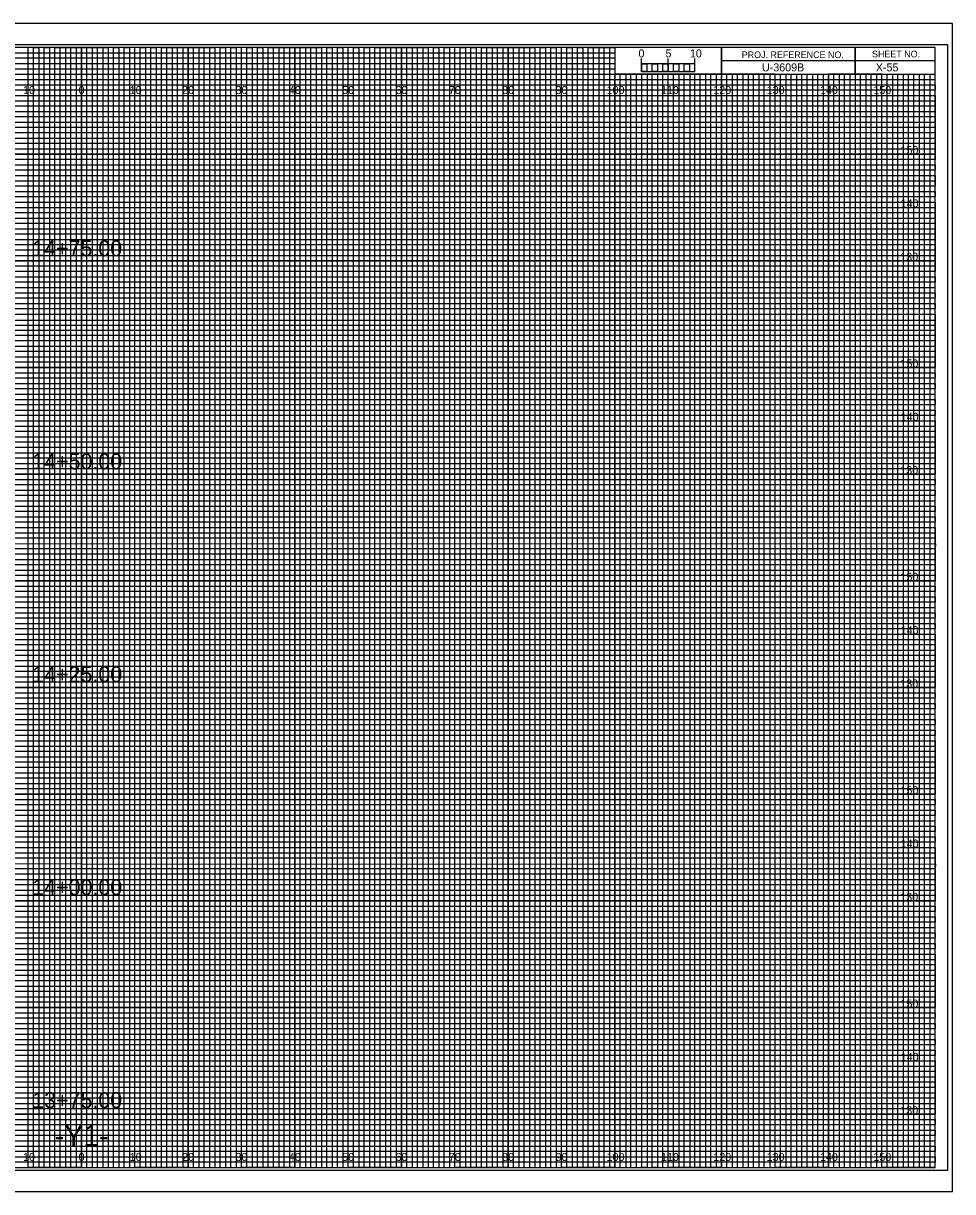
# Model space of a CAD drawing. Extents: x -13 to 323, y -5 to 2634.
# Drawn here: x 149.1 to 323.3, y 655.5 to 874.5 of the extents above; entities that cross this region are included whole.
import ezdxf

# ---------------------------------------------------------------- set-up
doc = ezdxf.new("R2010")
doc.units = 0
for name, color, linetype in [('Exist Cross Section Cell', 7, 'Continuous'), ('Exist XS Center Line Elevation Label', 7, 'Continuous'), ('Exist XS Ground Line', 7, 'Continuous'), ('Prop CMT Pvmt Course 1', 7, 'Continuous'), ('Prop CMT Pvmt Course 1 Wedge', 7, 'Continuous'), ('Prop CMT Pvmt Course 2', 7, 'Continuous'), ('Prop CMT Pvmt Course 2 Wedge', 7, 'Continuous'), ('Prop CMT Pvmt Course 3', 7, 'Continuous'), ('Prop CMT Pvmt Course 3 Wedge', 7, 'Continuous'), ('Prop CMT Pvmt Surface Shoulder', 7, 'Continuous'), ('Prop CMT Pvmt Wedge Surface 3', 7, 'Continuous'), ('Prop CMT Shld Paved Course 1', 7, 'Continuous'), ('Prop CMT Shld Paved Course 2', 7, 'Continuous'), ('Prop CMT Shld Paved Course 3', 7, 'Continuous'), ('Prop CMT Slope Grass', 7, 'Continuous'), ('Prop CMT Subgrade Earthwork', 7, 'Continuous'), ('Scratch_Level_0', 7, 'Continuous')]:
    doc.layers.add(name, color=color, linetype=linetype)

msp = doc.modelspace()

# ---------------------------------------------------------------- linework, layer by layer
at = {"layer": 'Exist XS Center Line Elevation Label'}
for points in [[(145, 660), (155, 660), (155, 870), (165, 870), (165, 660), (175, 660), (175, 870), (185, 870), (185, 660), (195, 660), (195, 870), (205, 870), (205, 660), (215, 660), (215, 870), (225, 870), (225, 660), (235, 660), (235, 870), (245, 870), (245, 660), (255, 660), (255, 870), (259.93, 870), (260, 870), (260, 865), (264.99, 865), (264.99, 660), (275, 660), (275, 865), (285, 865), (285, 660), (295, 660), (295, 865), (305, 865), (305, 660), (315, 660), (315, 865)], [(0, 865), (275, 865)], [(0, 845), (320, 845), (320, 855), (0, 855)], [(0, 825), (320, 825), (320, 835), (0, 835)], [(0, 805), (320, 805), (320, 815), (0, 815)], [(0, 785), (320, 785), (320, 795), (0, 795)], [(0, 765), (320, 765), (320, 775), (0, 775)], [(0, 745), (320, 745), (320, 755), (0, 755)], [(0, 725), (320, 725), (320, 735), (0, 735)], [(0, 705), (320, 705), (320, 715), (0, 715)], [(0, 685), (320, 685), (320, 695), (0, 695)], [(0, 665), (320, 665), (320, 675), (0, 675)]]:
    msp.add_lwpolyline(points, dxfattribs=at)
at = {"layer": 'Exist XS Ground Line'}
for p, q in [((150, 870), (140, 870)), ((150, 660), (150, 870)), ((170, 870), (160, 870)), ((160, 870), (160, 660)), ((170, 660), (170, 870)), ((190, 870), (180, 870)), ((180, 870), (180, 660)), ((190, 660), (190, 870)), ((210, 870), (200, 870)), ((200, 870), (200, 660)), ((210, 660), (210, 870)), ((230, 870), (220, 870)), ((220, 870), (220, 660)), ((230, 660), (230, 870)), ((250, 870), (240, 870)), ((240, 870), (240, 660)), ((250, 660), (250, 870)), ((260, 870), (260, 660)), ((270, 660), (270, 865)), ((290, 865), (280, 865)), ((280, 865), (280, 660)), ((290, 660), (290, 865)), ((310, 865), (300, 865)), ((300, 865), (300, 660)), ((310, 660), (310, 865)), ((160, 660), (150, 660)), ((180, 660), (170, 660)), ((200, 660), (190, 660)), ((220, 660), (210, 660)), ((240, 660), (230, 660)), ((260, 660), (250, 660)), ((280, 660), (270, 660)), ((300, 660), (290, 660)), ((320, 660), (310, 660)), ((320, 660), (320, 660))]:
    msp.add_line(p, q, dxfattribs=at)
for points in [[(0, 860), (320, 860), (320, 850), (0, 850)], [(0, 840), (320, 840), (320, 830), (0, 830)], [(0, 820), (320, 820), (320, 810), (0, 810)], [(0, 800), (320, 800), (320, 790), (0, 790)], [(0, 780), (320, 780), (320, 770), (0, 770)], [(0, 760), (320, 760), (320, 750), (0, 750)], [(0, 740), (320, 740), (320, 730), (0, 730)], [(0, 720), (320, 720), (320, 710), (0, 710)], [(0, 700), (320, 700), (320, 690), (0, 690)], [(0, 680), (320, 680), (320, 670), (0, 670)]]:
    msp.add_lwpolyline(points, dxfattribs=at)
at = {"layer": 'Prop CMT Pvmt Course 1'}
for p, q in [((265, 865.49), (265, 867.9)), ((265, 866.9), (265, 867.9)), ((270, 865.49), (270, 867.9)), ((275, 865.49), (275, 867.9)), ((275, 866.9), (275, 867.9))]:
    msp.add_line(p, q, dxfattribs=at)
for points in [[(275, 866.9), (265, 866.9), (265, 865.49), (275, 865.49)], [(265, 866.9), (266, 866.9), (266, 865.49), (265, 865.49)], [(267, 866.9), (268, 866.9), (268, 865.49), (267, 865.49)], [(269, 866.9), (270, 866.9), (270, 865.49), (269, 865.49)], [(271, 866.9), (272, 866.9), (272, 865.49), (271, 865.49)], [(273, 866.9), (274, 866.9), (274, 865.49), (273, 865.49)]]:
    msp.add_lwpolyline(points, close=True, dxfattribs=at)
at = {"layer": 'Prop CMT Pvmt Surface Shoulder'}
for p, q in [((267, 865), (266.01, 865)), ((266.01, 865), (266.01, 660)), ((267, 660), (267, 865)), ((269, 865), (268, 865)), ((268, 865), (268, 660)), ((269, 660), (269, 865)), ((266.01, 660), (265, 660)), ((268, 660), (267, 660))]:
    msp.add_line(p, q, dxfattribs=at)
for points in [[(150, 660), (151, 660), (151, 870), (152, 870), (152, 660)], [(152, 660), (153, 660), (153, 870), (154, 870), (154, 660)], [(155, 660), (156, 660), (156, 870), (157, 870), (157, 660)], [(157, 660), (158, 660), (158, 870), (159, 870), (159, 660)], [(160, 660), (161, 660), (161, 870), (162, 870), (162, 660)], [(162, 660), (163, 660), (163, 870), (164, 870), (164, 660)], [(165, 660), (166, 660), (166, 870), (167, 870), (167, 660)], [(167, 660), (168, 660), (168, 870), (169, 870), (169, 660)], [(170, 660), (171, 660), (171, 870), (172, 870), (172, 660)], [(172, 660), (173, 660), (173, 870), (174, 870), (174, 660)], [(175, 660), (176, 660), (176, 870), (177, 870), (177, 660)], [(177, 660), (178, 660), (178, 870), (179, 870), (179, 660)], [(180, 660), (181, 660), (181, 870), (182, 870), (182, 660)], [(182, 660), (183, 660), (183, 870), (184, 870), (184, 660)], [(185, 660), (186, 660), (186, 870), (187, 870), (187, 660)], [(187, 660), (188, 660), (188, 870), (189, 870), (189, 660)], [(190, 660), (191, 660), (191, 870), (192, 870), (192, 660)], [(192, 660), (193, 660), (193, 870), (194, 870), (194, 660)], [(195, 660), (196, 660), (196, 870), (197, 870), (197, 660)], [(197, 660), (198, 660), (198, 870), (199, 870), (199, 660)], [(200, 660), (201, 660), (201, 870), (202, 870), (202, 660)], [(202, 660), (203, 660), (203, 870), (204, 870), (204, 660)], [(205, 660), (206, 660), (206, 870), (207, 870), (207, 660)], [(207, 660), (208, 660), (208, 870), (209, 870), (209, 660)], [(210, 660), (211, 660), (211, 870), (212, 870), (212, 660)], [(212, 660), (213, 660), (213, 870), (214, 870), (214, 660)], [(215, 660), (216, 660), (216, 870), (217, 870), (217, 660)], [(217, 660), (218, 660), (218, 870), (219, 870), (219, 660)], [(220, 660), (221, 660), (221, 870), (222, 870), (222, 660)], [(222, 660), (223, 660), (223, 870), (224, 870), (224, 660)], [(225, 660), (226, 660), (226, 870), (227, 870), (227, 660)], [(227, 660), (228, 660), (228, 870), (229, 870), (229, 660)], [(230, 660), (231, 660), (231, 870), (232, 870), (232, 660)], [(232, 660), (233, 660), (233, 870), (234, 870), (234, 660)], [(235, 660), (236, 660), (236, 870), (237, 870), (237, 660)], [(237, 660), (238, 660), (238, 870), (239, 870), (239, 660)], [(240, 660), (241, 660), (241, 870), (242, 870), (242, 660)], [(242, 660), (243, 660), (243, 870), (244, 870), (244, 660)], [(245, 660), (246, 660), (246, 870), (247, 870), (247, 660)], [(247, 660), (248, 660), (248, 870), (249, 870), (249, 660)], [(250, 660), (251, 660), (251, 870), (252, 870), (252, 660)], [(252, 660), (253, 660), (253, 870), (254, 870), (254, 660)], [(255, 660), (256, 660), (256, 870), (257, 870), (257, 660)], [(257, 660), (258, 660), (258, 870), (259, 870), (259, 660)], [(260, 660), (261, 660), (261, 865), (262.02, 865), (262.02, 660)], [(262, 660), (263, 660), (263, 865), (263.99, 865), (263.99, 660)], [(270, 660), (270.98, 660), (270.98, 865), (272, 865), (272, 660)], [(272, 660), (273, 660), (273, 865), (274.05, 865), (274.05, 660)], [(275, 660), (276, 660), (276, 865), (277, 865), (277, 660)], [(277, 660), (278, 660), (278, 865), (279, 865), (279, 660)], [(280, 660), (281, 660), (281, 865), (282, 865), (282, 660)], [(282, 660), (283, 660), (283, 865), (284, 865), (284, 660)], [(285, 660), (286, 660), (286, 865), (287, 865), (287, 660)], [(287, 660), (288, 660), (288, 865), (289, 865), (289, 660)], [(290, 660), (291, 660), (291, 865), (292, 865), (292, 660)], [(292, 660), (293, 660), (293, 865), (294, 865), (294, 660)], [(295, 660), (296, 660), (296, 865), (297, 865), (297, 660)], [(297, 660), (298, 660), (298, 865), (299, 865), (299, 660)], [(300, 660), (301, 660), (301, 865), (302, 865), (302, 660)], [(302, 660), (303, 660), (303, 865), (304, 865), (304, 660)], [(305, 660), (306, 660), (306, 865), (307, 865), (307, 660)], [(307, 660), (308, 660), (308, 865), (309, 865), (309, 660)], [(310, 660), (311, 660), (311, 865), (312, 865), (312, 660)], [(312, 660), (313, 660), (313, 865), (314, 865), (314, 660)], [(315, 660), (316, 660), (316, 865), (317, 865), (317, 660)], [(317, 660), (318, 660), (318, 865), (319, 865), (319, 660)]]:
    msp.add_lwpolyline(points, dxfattribs=at)
at = {"layer": 'Prop CMT Pvmt Wedge Surface 3'}
for p, q in [((305, 870), (305, 865)), ((305, 865), (305, 870)), ((280, 867.5), (280, 865)), ((320, 867.49), (280, 867.49)), ((280, 865), (320, 865))]:
    msp.add_line(p, q, dxfattribs=at)
for points in [[(320, 870), (0, 870), (0, 660), (320, 660)], [(280, 870), (260, 870), (260, 865.03), (280, 865.03)], [(320, 870), (280, 870), (280, 865), (320, 865)]]:
    msp.add_lwpolyline(points, close=True, dxfattribs=at)
at = {"layer": 'Prop CMT Shld Paved Course 1'}
for p, q in [((150, 660), (150, 870)), ((160, 660), (160, 870)), ((170, 660), (170, 870)), ((180, 660), (180, 870)), ((190, 660), (190, 870)), ((200, 660), (200, 870)), ((210, 660), (210, 870)), ((220, 660), (220, 870)), ((230, 660), (230, 870)), ((240, 660), (240, 870)), ((250, 660), (250, 870)), ((260, 660), (260, 864.69)), ((270, 660), (270, 864.69)), ((280, 660), (280, 864.69)), ((290, 660), (290, 864.69)), ((300, 660), (300, 864.69)), ((310, 660), (310, 864.69)), ((0, 860), (320, 860)), ((0, 850), (320, 850)), ((0, 840), (320, 840)), ((0, 830), (320, 830)), ((0, 820), (320, 820)), ((0, 810), (320, 810)), ((0, 800), (320, 800)), ((0, 790), (320, 790)), ((0, 780), (320, 780)), ((0, 770), (320, 770)), ((0, 760), (320, 760)), ((0, 750), (320, 750)), ((0, 740), (320, 740)), ((0, 730), (320, 730)), ((0, 720), (320, 720)), ((0, 710), (320, 710)), ((0, 700), (320, 700)), ((0, 690), (320, 690)), ((0, 680), (320, 680)), ((0, 670), (320, 670))]:
    msp.add_line(p, q, dxfattribs=at)
at = {"layer": 'Prop CMT Shld Paved Course 2'}
for p, q in [((323.3, 874.5), (-13.4, 874.5)), ((-13.4, 655.5), (323.3, 655.5))]:
    msp.add_line(p, q, dxfattribs=at)
at = {"layer": 'Prop CMT Slope Grass'}
msp.add_lwpolyline([(-10.8, 659.5), (322.4, 659.5), (322.4, 870.5), (-10.8, 870.5)], close=True, dxfattribs=at)
at = {"layer": 'Prop CMT Subgrade Earthwork'}
msp.add_lwpolyline([(-13.4, 655.5), (323.3, 655.5), (323.3, 874.5), (-13.4, 874.5)], close=True, dxfattribs=at)
at = {"layer": 'Scratch_Level_0'}
for p, q in [((0, 869), (260, 869)), ((260, 867.98), (0, 867.98)), ((260, 869), (260, 867.98)), ((0, 867), (260, 867)), ((260, 865.89), (0, 865.89)), ((260, 867), (260, 865.89)), ((0, 864), (320, 864))]:
    msp.add_line(p, q, dxfattribs=at)
for points in [[(0, 863), (270, 863), (320, 863), (320, 862), (0, 862)], [(0, 861), (320, 861), (320, 859), (0, 859)], [(0, 858), (320, 858), (320, 857), (0, 856.98)], [(0, 856), (320, 856), (320, 854), (0, 854)], [(0, 853), (320, 853), (320, 852), (0, 852)], [(0, 851), (320, 851), (320, 849), (0, 849)], [(0, 848), (320, 848), (320, 847), (0, 847)], [(0, 846), (320, 846), (320, 844), (0, 844)], [(0, 843), (320, 843), (320, 842), (0, 842)], [(0, 841), (320, 841), (320, 839), (0, 839)], [(0, 838), (320, 838), (320, 837), (0, 837)], [(0, 836), (320, 836), (320, 833.95), (320, 833), (320, 832), (0, 832)], [(0, 834), (320, 834), (320, 833), (0, 833)], [(0, 831), (320, 831), (320, 829), (0, 829.03)], [(0, 829.03), (320, 829), (320, 828), (0, 828)], [(0, 827), (320, 827), (320, 826), (0, 826)], [(0, 824), (320, 824), (320, 823), (0, 823)], [(0, 822), (320, 822), (320, 821), (0, 821)], [(-0.07, 818.89), (320, 818.89), (320, 817.88), (-0.07, 817.88)], [(0, 817), (320, 817), (320, 816), (0, 816)], [(0, 814), (320, 814), (320, 813), (0, 813)], [(0, 812), (320, 812), (320, 811), (0, 811)], [(0, 809), (320, 809), (320, 808), (0, 808)], [(0, 807), (320, 807), (320, 806), (0, 806)], [(0, 804), (320, 804), (320, 803), (0, 803)], [(0, 802), (320, 802), (320, 801), (0, 801)], [(0, 799), (320, 799), (319.99, 797.98), (0, 798)], [(0, 797), (320, 797), (320, 796), (0, 796)], [(0, 794), (320, 794), (320, 793), (0, 793)], [(0, 792), (320, 792), (320, 791), (0, 791)], [(0, 789), (320, 789), (320, 788), (0, 788)], [(0, 787), (320, 787), (320, 786), (0, 786)], [(0, 784), (320, 784), (320, 783), (0, 783)], [(0, 782), (320, 782), (320, 781), (0, 781)], [(0, 779), (320, 779), (320, 778), (0, 778)], [(0, 776.99), (320.07, 776.91), (320, 776), (0, 776)], [(0, 774), (320, 774), (320, 773), (0, 773)], [(0, 772), (320, 772), (320, 771), (0, 771)], [(0, 769), (320, 769), (320, 768), (0, 768)], [(0, 767), (320, 767), (320, 766), (0, 766)], [(0, 764), (320, 764), (320, 763), (0, 763)], [(0, 762), (320, 762), (320, 761), (0, 761)], [(0, 759), (320, 759), (320, 758), (0, 758)], [(0, 757), (320, 757), (320, 756), (0, 756)], [(0, 754), (320, 754), (320, 753), (0, 753)], [(0, 752), (320, 752), (320, 751), (0, 751)], [(0, 749), (320, 749), (320, 748), (0, 748)], [(0, 747), (320, 747), (320, 746), (0, 746)], [(0, 744), (320, 744), (320, 743), (0, 743)], [(0, 742), (320, 742), (320, 741), (0, 741)], [(0, 739), (320, 739), (319.99, 737.98), (0, 738)], [(0, 737), (320, 737), (320, 736), (0, 736)], [(0, 734), (320, 734), (320, 733), (0, 733)], [(0, 732), (320, 732), (320, 731), (0, 731)], [(0, 729), (320, 729), (320, 728), (0, 728)], [(0, 727), (320, 727), (320, 726), (0, 726)], [(0, 724), (320, 724), (320, 723), (0, 723)], [(0, 722), (320, 722), (320, 721), (0, 721)], [(0, 719), (320, 719), (320, 718), (0, 718)], [(0, 716.99), (320.07, 716.91), (320, 716), (0, 716)], [(0, 714), (320, 714), (320, 713), (0, 713)], [(0, 712), (320, 712), (320, 711), (0, 711)], [(0, 709), (320, 709), (320, 708), (0, 708)], [(0, 707), (320, 707), (320, 706), (0, 706)], [(0, 704), (320, 704), (320, 703), (0, 703)], [(0, 702), (320, 702), (320, 701), (0, 701)], [(0, 699), (320, 699), (320, 698), (0, 698)], [(0, 697), (320, 697), (320, 696), (0, 696)], [(0, 694), (320, 694), (320, 693), (0, 693)], [(0, 692), (320, 692), (320, 691), (0, 691)], [(0, 689), (320, 689), (320, 688), (0, 688)], [(0, 687), (320, 687), (320, 686), (0, 686)], [(0, 684), (320, 684), (320, 683), (0, 683)], [(0, 682), (320, 682), (320, 681), (0, 681)], [(0, 679), (320, 679), (320, 678), (0, 678)], [(0, 677), (320, 677), (320, 676), (0, 676)], [(0, 674), (320, 674), (320, 673), (0, 673)], [(0, 672), (320, 672), (320, 671), (0, 671)], [(0, 669), (320, 669), (320, 668), (0, 668)], [(0, 667), (320, 667), (320, 666), (0, 666)], [(0, 664), (320, 664), (320, 663), (0, 663)], [(0, 662), (320, 662), (320, 661), (0, 661)]]:
    msp.add_lwpolyline(points, dxfattribs=at)

# ---------------------------------------------------------------- texts
at = {"layer": 'Exist Cross Section Cell'}
for s, p in [('10', (149.04, 861.25)), ('0', (159.45, 861.25)), ('0', (159.45, 861.25)), ('10', (169.04, 861.25)), ('20', (178.86, 861.25)), ('30', (188.86, 861.25)), ('40', (198.86, 861.25)), ('50', (208.86, 861.25)), ('60', (218.86, 861.25)), ('70', (228.86, 861.25)), ('80', (238.86, 861.25)), ('90', (248.86, 861.25)), ('100', (258.44, 861.25)), ('110', (268.62, 861.25)), ('120', (278.44, 861.25)), ('130', (288.44, 861.25)), ('140', (298.44, 861.25)), ('150', (308.44, 861.25)), ('10', (149.04, 661.25)), ('0', (159.45, 661.25)), ('0', (159.45, 661.25)), ('10', (169.04, 661.25)), ('20', (178.86, 661.25)), ('30', (188.86, 661.25)), ('40', (198.86, 661.25)), ('50', (208.86, 661.25)), ('60', (218.86, 661.25)), ('70', (228.86, 661.25)), ('80', (238.86, 661.25)), ('90', (248.86, 661.25)), ('100', (258.44, 661.25)), ('110', (268.62, 661.25)), ('120', (278.44, 661.25)), ('130', (288.44, 661.25)), ('140', (298.44, 661.25)), ('150', (308.44, 661.25))]:
    msp.add_text(s, height=1.5, dxfattribs=at).set_placement(p)
at = {"layer": 'Prop CMT Pvmt Course 1'}
msp.add_text('0', height=1.5, dxfattribs=at).set_placement((264.41, 868.12))
at = {"layer": 'Prop CMT Pvmt Course 1 Wedge'}
msp.add_text('U-3609B', height=1.5, dxfattribs=at).set_placement((287.56, 865.5))
at = {"layer": 'Prop CMT Pvmt Course 2'}
for s, p in [('14+75.00', (150.77, 830.83)), ('14+50.00', (150.77, 790.89)), ('14+25.00', (150.77, 750.98)), ('14+00.00', (150.77, 711.07)), ('13+75.00', (150.77, 671.16))]:
    msp.add_text(s, height=3, dxfattribs=at).set_placement(p)
at = {"layer": 'Prop CMT Pvmt Course 2 Wedge'}
msp.add_text('-Y1-', height=4, dxfattribs=at).set_placement((154.99, 664))
at = {"layer": 'Prop CMT Pvmt Course 3'}
msp.add_text('X-55', height=1.5, dxfattribs=at).set_placement((308.9, 865.5))
at = {"layer": 'Prop CMT Pvmt Course 3 Wedge'}
for s, p in [('5', (269.47, 868.12)), ('10', (274.04, 868.12))]:
    msp.add_text(s, height=1.5, dxfattribs=at).set_placement(p)
at = {"layer": 'Prop CMT Pvmt Wedge Surface 3'}
for s, p in [('PROJ. REFERENCE NO.', (283.77, 867.99)), ('SHEET NO.', (308.19, 868.12))]:
    msp.add_text(s, height=1.25, dxfattribs=at).set_placement(p)
at = {"layer": 'Prop CMT Shld Paved Course 3'}
for s, p in [('150', (313.52, 850)), ('140', (313.57, 840)), ('130', (313.49, 830)), ('150', (313.52, 810)), ('140', (313.57, 800)), ('130', (313.49, 790)), ('150', (313.52, 770)), ('140', (313.57, 760)), ('130', (313.49, 750)), ('150', (313.52, 730)), ('140', (313.57, 720)), ('130', (313.49, 710)), ('150', (313.52, 690)), ('140', (313.57, 680)), ('130', (313.49, 670))]:
    msp.add_text(s, height=1.5, dxfattribs=at).set_placement(p)

doc.saveas('drawing.dxf')
